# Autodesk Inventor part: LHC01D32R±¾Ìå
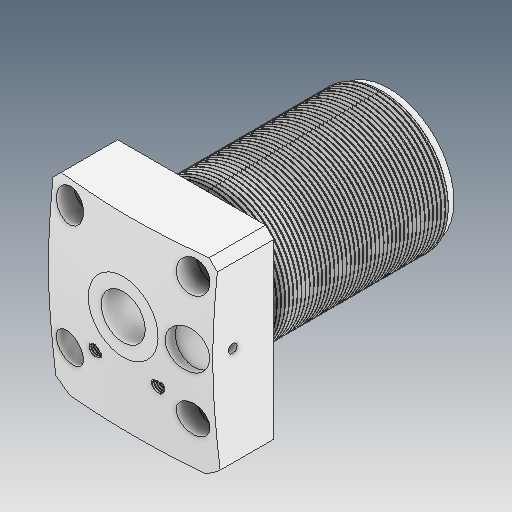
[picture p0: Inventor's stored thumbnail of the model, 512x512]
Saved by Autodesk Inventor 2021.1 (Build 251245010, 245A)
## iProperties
Created: 2021-06
Part Number: LHC01D32R±¾Ìå
Material: Ogólny
Document SubType Name: Modeling
Designer: user
Density: 1 g/cm^3
Appearance: Domyślna
Author: user
Revision Number: ÈÎºÎ
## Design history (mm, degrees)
feature "NONE"
node "Bryła1"
